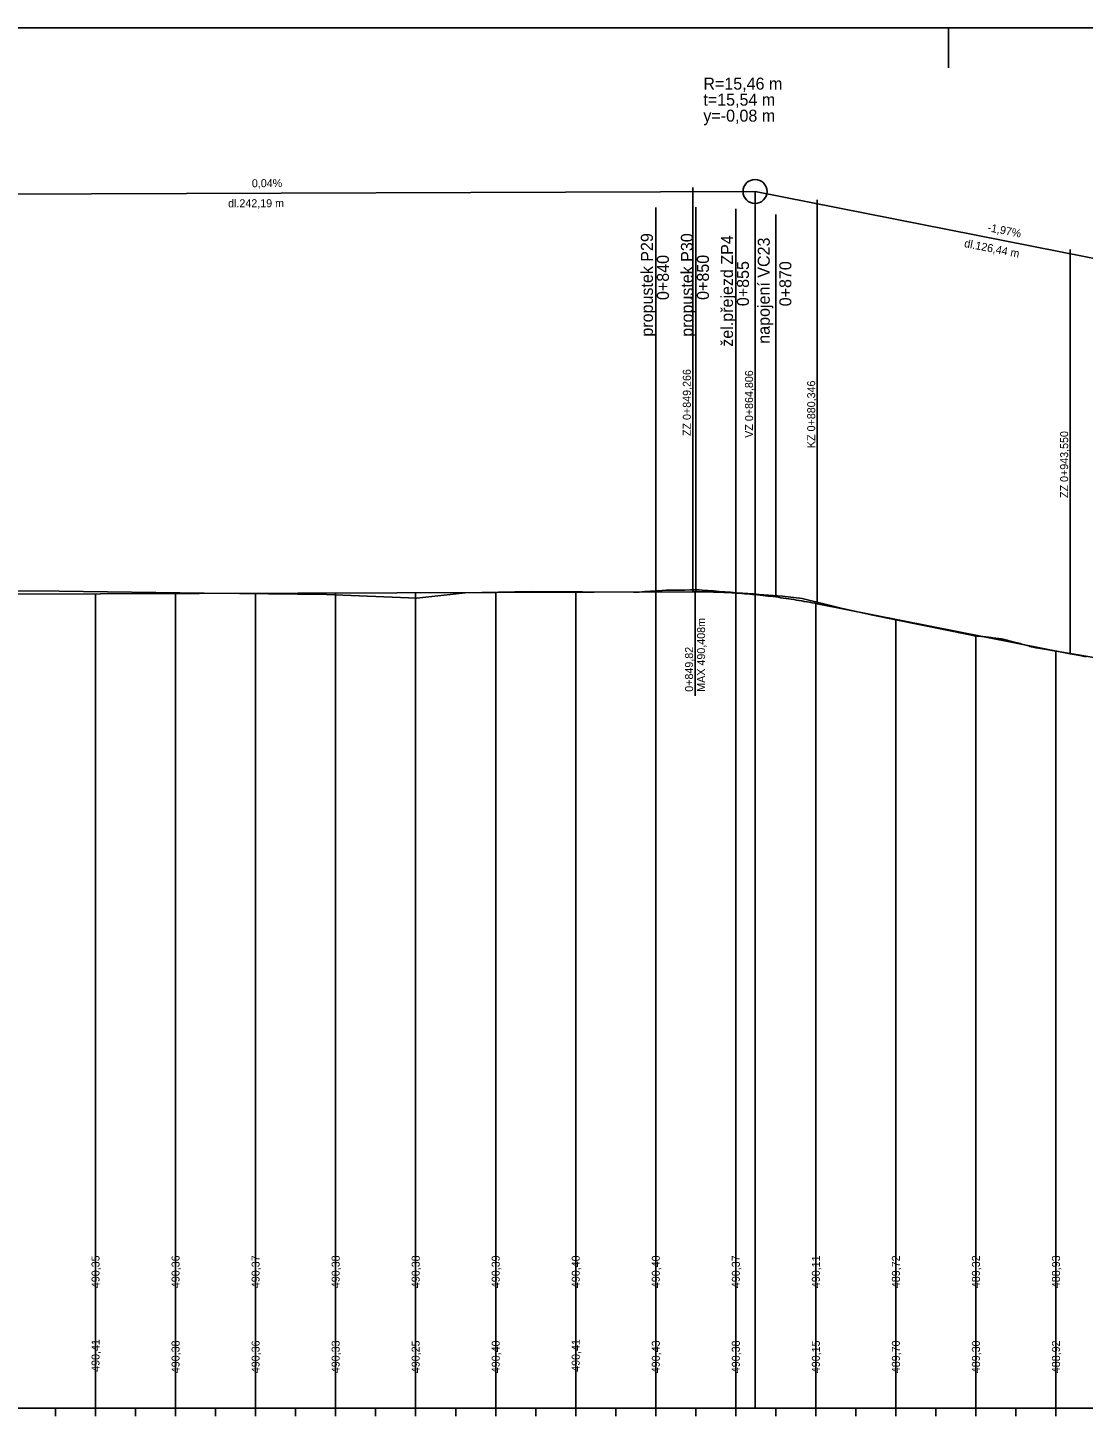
# Model space of a CAD drawing. Extents: x -632716 to -629545, y -1094726 to -1088285.
# Drawn here: x -631800.3 to -631536.7, y -1091019.4 to -1090670.2 of the extents above; entities that cross this region are included whole.
import ezdxf

# ---------------------------------------------------------------- set-up
doc = ezdxf.new("R2010")
doc.units = 0
for name, color, linetype in [('20', 7, 'Continuous'), ('Default', 7, 'Continuous'), ('formát', 7, 'Continuous'), ('NIVELETA_VYSKY', 7, 'Continuous'), ('REZ_TENKA', 7, 'Continuous'), ('REZ_TLUSTA', 7, 'Continuous'), ('SKLONY_NIVELETA', 7, 'Continuous'), ('SKLONY_POPIS', 7, 'Continuous'), ('TECNY_NIVELETA', 7, 'Continuous'), ('TEREN_VYSKY', 7, 'Continuous'), ('VOZOVKA', 7, 'Continuous')]:
    doc.layers.add(name, color=color, linetype=linetype)

msp = doc.modelspace()

# ---------------------------------------------------------------- linework, layer by layer
at = {"layer": '20'}
for points in [[(-631783.46, -1090811.65), (-631783.46, -1090965.2), (-631783.46, -1091015.2), (-631783.46, -1090955.2)], [(-631763.46, -1090811.58), (-631763.46, -1090965.2), (-631763.46, -1091015.2), (-631763.46, -1090955.2)], [(-631743.46, -1090811.51), (-631743.46, -1090965.2), (-631743.46, -1091015.2), (-631743.46, -1090955.2)], [(-631723.46, -1090811.44), (-631723.46, -1090965.2), (-631723.46, -1091015.2), (-631723.46, -1090955.2)], [(-631703.46, -1090811.37), (-631703.46, -1090965.2), (-631703.46, -1091015.2), (-631703.46, -1090955.2)], [(-631683.46, -1090811.3), (-631683.46, -1090965.2), (-631683.46, -1091015.2), (-631683.46, -1090955.2)], [(-631663.46, -1090811.22), (-631663.46, -1090965.2), (-631663.46, -1091015.2), (-631663.46, -1090955.2)], [(-631643.46, -1090811.15), (-631643.46, -1090965.2), (-631643.46, -1091015.2), (-631643.46, -1090955.2)], [(-631623.46, -1090811.45), (-631623.46, -1090965.2), (-631623.46, -1091015.2), (-631623.46, -1090955.2)], [(-631603.46, -1090814.06), (-631603.46, -1090965.2), (-631603.46, -1091015.2), (-631603.46, -1090955.2)], [(-631583.46, -1090818.01), (-631583.46, -1090965.2), (-631583.46, -1091015.2), (-631583.46, -1090955.2)], [(-631563.46, -1090821.96), (-631563.46, -1090965.2), (-631563.46, -1091015.2), (-631563.46, -1090955.2)], [(-631543.46, -1090825.91), (-631543.46, -1090965.2), (-631543.46, -1091015.2), (-631543.46, -1090955.2)]]:
    msp.add_lwpolyline(points, dxfattribs=at)
at = {"layer": 'Default'}
for p, q in [((-631806.88, -1090811.74), (-631634.2, -1090811.12)), ((-631806.88, -1090811.74), (-631634.2, -1090811.12)), ((-631603.12, -1090814.13), (-631539.91, -1090826.61)), ((-631603.12, -1090814.13), (-631539.91, -1090826.61))]:
    msp.add_line(p, q, dxfattribs=at)
for points in [[(-631634.2, -1090811.12), (-631633.55, -1090811.12), (-631632.9, -1090811.12), (-631632.26, -1090811.13), (-631631.61, -1090811.13), (-631630.96, -1090811.14), (-631630.31, -1090811.16), (-631629.67, -1090811.17), (-631629.02, -1090811.19), (-631628.37, -1090811.21), (-631627.72, -1090811.23), (-631627.08, -1090811.26), (-631626.43, -1090811.29), (-631625.78, -1090811.32), (-631625.13, -1090811.35), (-631624.49, -1090811.39), (-631623.84, -1090811.43), (-631623.19, -1090811.47), (-631622.54, -1090811.52), (-631621.9, -1090811.57), (-631621.25, -1090811.62), (-631620.6, -1090811.67), (-631619.95, -1090811.73), (-631619.31, -1090811.78), (-631618.01, -1090811.91), (-631617.36, -1090811.98), (-631616.72, -1090812.05), (-631616.07, -1090812.12), (-631615.42, -1090812.19), (-631614.77, -1090812.27), (-631614.13, -1090812.35), (-631613.48, -1090812.43), (-631612.83, -1090812.52), (-631612.18, -1090812.61), (-631611.54, -1090812.7), (-631610.89, -1090812.79), (-631610.24, -1090812.89), (-631609.59, -1090812.99), (-631608.95, -1090813.09), (-631608.3, -1090813.2), (-631607.65, -1090813.3), (-631607, -1090813.41), (-631606.36, -1090813.53), (-631605.71, -1090813.64), (-631605.06, -1090813.76), (-631604.41, -1090813.88), (-631603.77, -1090814.01), (-631603.12, -1090814.13)], [(-631634.2, -1090811.12), (-631633.55, -1090811.12), (-631632.9, -1090811.12), (-631632.26, -1090811.13), (-631631.61, -1090811.13), (-631630.96, -1090811.14), (-631630.31, -1090811.16), (-631629.67, -1090811.17), (-631629.02, -1090811.19), (-631628.37, -1090811.21), (-631627.72, -1090811.23), (-631627.08, -1090811.26), (-631626.43, -1090811.29), (-631625.78, -1090811.32), (-631625.13, -1090811.35), (-631624.49, -1090811.39), (-631623.84, -1090811.43), (-631623.19, -1090811.47), (-631622.54, -1090811.52), (-631621.9, -1090811.57), (-631621.25, -1090811.62), (-631620.6, -1090811.67), (-631619.95, -1090811.73), (-631619.31, -1090811.78), (-631618.01, -1090811.91), (-631617.36, -1090811.98), (-631616.72, -1090812.05), (-631616.07, -1090812.12), (-631615.42, -1090812.19), (-631614.77, -1090812.27), (-631614.13, -1090812.35), (-631613.48, -1090812.43), (-631612.83, -1090812.52), (-631612.18, -1090812.61), (-631611.54, -1090812.7), (-631610.89, -1090812.79), (-631610.24, -1090812.89), (-631609.59, -1090812.99), (-631608.95, -1090813.09), (-631608.3, -1090813.2), (-631607.65, -1090813.3), (-631607, -1090813.41), (-631606.36, -1090813.53), (-631605.71, -1090813.64), (-631605.06, -1090813.76), (-631604.41, -1090813.88), (-631603.77, -1090814.01), (-631603.12, -1090814.13)], [(-631539.91, -1090826.61), (-631537.93, -1090827), (-631535.94, -1090827.38)], [(-631539.91, -1090826.61), (-631537.93, -1090827), (-631535.94, -1090827.38)]]:
    msp.add_lwpolyline(points, dxfattribs=at)
at = {"layer": 'formát'}
msp.add_line((-631570.3, -1090680.2), (-631570.3, -1090670.2), dxfattribs=at)
msp.add_lwpolyline([(-632585.29, -1091264.2), (-630730.3, -1091264.2), (-630730.3, -1090670.2), (-632585.29, -1090670.2)], close=True, dxfattribs=at)
at = {"layer": 'REZ_TENKA'}
for p, q in [((-631793.46, -1091017.2), (-631793.46, -1091015.2)), ((-631773.46, -1091017.2), (-631773.46, -1091015.2)), ((-631763.46, -1091017.2), (-631763.46, -1091015.2)), ((-631753.46, -1091017.2), (-631753.46, -1091015.2)), ((-631743.46, -1091017.2), (-631743.46, -1091015.2)), ((-631733.46, -1091017.2), (-631733.46, -1091015.2)), ((-631723.46, -1091017.2), (-631723.46, -1091015.2)), ((-631713.46, -1091017.2), (-631713.46, -1091015.2)), ((-631703.46, -1091017.2), (-631703.46, -1091015.2)), ((-631693.46, -1091017.2), (-631693.46, -1091015.2)), ((-631673.46, -1091017.2), (-631673.46, -1091015.2)), ((-631663.46, -1091017.2), (-631663.46, -1091015.2)), ((-631653.46, -1091017.2), (-631653.46, -1091015.2)), ((-631643.46, -1091017.2), (-631643.46, -1091015.2)), ((-631633.46, -1091017.2), (-631633.46, -1091015.2)), ((-631623.46, -1091017.2), (-631623.46, -1091015.2)), ((-631613.46, -1091017.2), (-631613.46, -1091015.2)), ((-631603.46, -1091017.2), (-631603.46, -1091015.2)), ((-631593.46, -1091017.2), (-631593.46, -1091015.2)), ((-631573.46, -1091017.2), (-631573.46, -1091015.2)), ((-631563.46, -1091017.2), (-631563.46, -1091015.2)), ((-631553.46, -1091017.2), (-631553.46, -1091015.2)), ((-631543.46, -1091017.2), (-631543.46, -1091015.2))]:
    msp.add_line(p, q, dxfattribs=at)
at = {"layer": 'REZ_TLUSTA'}
for p, q in [((-631783.46, -1091017.2), (-631783.46, -1091013.2)), ((-631683.46, -1091017.2), (-631683.46, -1091013.2)), ((-631583.46, -1091017.2), (-631583.46, -1091013.2)), ((-632483.46, -1091015.2), (-630763.46, -1091015.2))]:
    msp.add_line(p, q, dxfattribs=at)
at = {"layer": 'SKLONY_NIVELETA'}
for p, q in [((-631860.84, -1090711.93), (-631618.66, -1090711.06)), ((-631618.66, -1090711.06), (-631618.66, -1091015.2)), ((-631618.66, -1090711.06), (-631492.21, -1090736.03)), ((-631613.46, -1090716.81), (-631613.46, -1090812.4)), ((-631806.88, -1090811.74), (-631634.2, -1090811.12)), ((-631603.12, -1090814.13), (-631539.91, -1090826.61))]:
    msp.add_line(p, q, dxfattribs=at)
for points in [[(-631634.2, -1090811.12), (-631633.55, -1090811.12), (-631632.9, -1090811.12), (-631632.26, -1090811.13), (-631631.61, -1090811.13), (-631630.96, -1090811.14), (-631630.31, -1090811.16), (-631629.67, -1090811.17), (-631629.02, -1090811.19), (-631628.37, -1090811.21), (-631627.72, -1090811.23), (-631627.08, -1090811.26), (-631626.43, -1090811.29), (-631625.78, -1090811.32), (-631625.13, -1090811.35), (-631624.49, -1090811.39), (-631623.84, -1090811.43), (-631623.19, -1090811.47), (-631622.54, -1090811.52), (-631621.9, -1090811.57), (-631621.25, -1090811.62), (-631620.6, -1090811.67), (-631619.95, -1090811.73), (-631619.31, -1090811.78), (-631618.01, -1090811.91), (-631617.36, -1090811.98), (-631616.72, -1090812.05), (-631616.07, -1090812.12), (-631615.42, -1090812.19), (-631614.77, -1090812.27), (-631614.13, -1090812.35), (-631613.48, -1090812.43), (-631612.83, -1090812.52), (-631612.18, -1090812.61), (-631611.54, -1090812.7), (-631610.89, -1090812.79), (-631610.24, -1090812.89), (-631609.59, -1090812.99), (-631608.95, -1090813.09), (-631608.3, -1090813.2), (-631607.65, -1090813.3), (-631607, -1090813.41), (-631606.36, -1090813.53), (-631605.71, -1090813.64), (-631605.06, -1090813.76), (-631604.41, -1090813.88), (-631603.77, -1090814.01), (-631603.12, -1090814.13)], [(-631539.91, -1090826.61), (-631537.93, -1090827), (-631535.94, -1090827.38)]]:
    msp.add_lwpolyline(points, dxfattribs=at)
msp.add_circle((-631618.66, -1090711.06), 3, dxfattribs=at)
at = {"layer": 'TECNY_NIVELETA'}
for p, q in [((-631634.2, -1090811.12), (-631634.2, -1090710.12)), ((-631618.66, -1090711.06), (-631618.66, -1090711.06)), ((-631603.12, -1090814.13), (-631603.12, -1090713.13)), ((-631643.46, -1090811.15), (-631643.46, -1090715.06)), ((-631633.46, -1090811.12), (-631633.46, -1090715.02)), ((-631623.46, -1090811.42), (-631623.46, -1090715.43)), ((-631539.91, -1090826.61), (-631539.91, -1090725.61)), ((-631633.64, -1090811.12), (-631633.64, -1090837.12))]:
    msp.add_line(p, q, dxfattribs=at)
at = {"layer": 'VOZOVKA'}
msp.add_lwpolyline([(-631803.55, -1090810.88), (-631792.58, -1090810.98), (-631756.27, -1090811.45), (-631747.46, -1090811.58), (-631725.76, -1090811.85), (-631703.16, -1090812.7), (-631691.13, -1090811.37), (-631674.5, -1090811.1), (-631649.02, -1090811.2), (-631647.67, -1090811.21), (-631647.6, -1090811.2), (-631646.17, -1090811.1), (-631644.74, -1090811), (-631643.31, -1090810.9), (-631641.89, -1090810.81), (-631640.9, -1090810.74), (-631640.46, -1090810.74), (-631639.03, -1090810.72), (-631637.6, -1090810.71), (-631636.18, -1090810.69), (-631634.75, -1090810.68), (-631633.32, -1090810.67), (-631632.61, -1090810.66), (-631631.9, -1090810.72), (-631630.47, -1090810.82), (-631629.04, -1090810.93), (-631627.61, -1090811.04), (-631626.19, -1090811.15), (-631624.76, -1090811.26), (-631623.33, -1090811.37), (-631621.9, -1090811.48), (-631621.77, -1090811.49), (-631620.48, -1090811.58), (-631619.05, -1090811.68), (-631617.62, -1090811.78), (-631611.79, -1090812.2), (-631606.91, -1090812.82), (-631597.13, -1090815.2), (-631589.6, -1090816.93), (-631564.94, -1090821.93), (-631564.58, -1090822.01), (-631564.22, -1090822.08), (-631563.91, -1090822.14), (-631563.86, -1090822.14), (-631563.51, -1090822.17), (-631563.15, -1090822.2), (-631562.79, -1090822.23), (-631562.44, -1090822.25), (-631562.08, -1090822.28), (-631561.87, -1090822.3), (-631561.72, -1090822.32), (-631561.36, -1090822.36), (-631561.01, -1090822.41), (-631560.65, -1090822.46), (-631560.29, -1090822.51), (-631559.94, -1090822.56), (-631559.58, -1090822.6), (-631559.22, -1090822.65), (-631558.86, -1090822.7), (-631558.5, -1090822.75), (-631558.14, -1090822.79), (-631557.78, -1090822.84), (-631557.42, -1090822.88), (-631557.06, -1090822.93), (-631556.7, -1090822.97), (-631556.63, -1090822.98), (-631556.34, -1090823.06), (-631555.98, -1090823.16), (-631555.62, -1090823.26), (-631555.26, -1090823.36), (-631554.9, -1090823.46), (-631554.83, -1090823.48), (-631554.54, -1090823.55), (-631554.18, -1090823.64), (-631553.82, -1090823.73), (-631553.46, -1090823.82), (-631553.1, -1090823.92), (-631552.74, -1090824.01), (-631552.39, -1090824.1), (-631552.03, -1090824.2), (-631551.67, -1090824.29), (-631551.31, -1090824.39), (-631550.96, -1090824.49), (-631550.6, -1090824.59), (-631550.24, -1090824.68), (-631549.89, -1090824.78), (-631549.75, -1090824.82), (-631549.53, -1090824.87), (-631549.17, -1090824.95), (-631548.81, -1090825.04), (-631548.46, -1090825.12), (-631548.29, -1090825.16), (-631525.08, -1090829.09)], dxfattribs=at)

# ---------------------------------------------------------------- texts
at = {"layer": 'NIVELETA_VYSKY'}
for s, p in [('490,35', (-631782.46, -1090985.2)), ('490,36', (-631762.46, -1090985.2)), ('490,37', (-631742.46, -1090985.2)), ('490,38', (-631722.46, -1090985.2)), ('490,38', (-631702.46, -1090985.2)), ('490,39', (-631682.46, -1090985.2)), ('490,40', (-631662.46, -1090985.2)), ('490,40', (-631642.46, -1090985.2)), ('490,37', (-631622.46, -1090985.2)), ('490,11', (-631602.46, -1090985.2)), ('489,72', (-631582.46, -1090985.2)), ('489,32', (-631562.46, -1090985.2)), ('488,93', (-631542.46, -1090985.2))]:
    msp.add_text(s, height=2, rotation=90, dxfattribs=at).set_placement(p)
at = {"layer": 'SKLONY_POPIS'}
for s, p in [('R=15,46 m', (-631631.57, -1090685.62)), ('t=15,54 m', (-631631.57, -1090689.62)), ('y=-0,08 m', (-631631.57, -1090693.62))]:
    msp.add_text(s, height=3, dxfattribs=at).set_placement(p)
for s, height, rotation, p in [('0,04%', 2, 0.2049, (-631744.39, -1090710.01)), ('dl.242,19 m', 2, 0.2049, (-631750.33, -1090715.04)), ('-1,97%', 2, 348.8332, (-631560.67, -1090720.98)), ('propustek P29', 3, 90, (-631644.18, -1090747.36)), ('propustek P30', 3, 90, (-631634.18, -1090747.39)), ('žel.přejezd ZP4', 3, 90, (-631624.18, -1090749.88)), ('napojení VC23', 3, 90, (-631614.98, -1090749.13)), ('dl.126,44 m', 2, 348.8332, (-631566.5, -1090724.93)), ('0+840', 3, 90, (-631640.18, -1090738.21)), ('0+850', 3, 90, (-631630.18, -1090738.18)), ('0+855', 3, 90, (-631620.18, -1090739.74)), ('0+870', 3, 90, (-631609.58, -1090739.78)), ('ZZ 0+849,266', 2, 90, (-631634.7, -1090772.2)), ('VZ 0+864,806', 2, 90, (-631619.16, -1090772.65)), ('KZ 0+880,346', 2, 90, (-631603.62, -1090775.21)), ('ZZ 0+943,550', 2, 90, (-631540.41, -1090787.69)), ('MAX 490,408m', 2, 90, (-631631.14, -1090836.12)), ('0+849,82', 2, 90, (-631634.14, -1090836.12))]:
    msp.add_text(s, height=height, rotation=rotation, dxfattribs=at).set_placement(p)
at = {"layer": 'TEREN_VYSKY'}
for s, p in [('490,41', (-631782.46, -1091006.12)), ('490,38', (-631762.46, -1091006.46)), ('490,36', (-631742.46, -1091006.46)), ('490,33', (-631722.46, -1091006.46)), ('490,25', (-631702.46, -1091006.46)), ('490,40', (-631682.46, -1091006.46)), ('490,41', (-631662.46, -1091006.12)), ('490,43', (-631642.46, -1091006.46)), ('490,38', (-631622.46, -1091006.46)), ('490,15', (-631602.46, -1091006.46)), ('489,70', (-631582.46, -1091006.46)), ('489,30', (-631562.46, -1091006.46)), ('488,92', (-631542.46, -1091006.46))]:
    msp.add_text(s, height=2, rotation=90, dxfattribs=at).set_placement(p)

doc.saveas('drawing.dxf')
